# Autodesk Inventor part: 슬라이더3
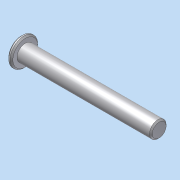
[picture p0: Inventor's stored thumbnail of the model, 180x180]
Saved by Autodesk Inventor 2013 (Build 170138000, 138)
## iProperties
Company: 한국ATC센터
Created: 2015-04
Part Number: 슬라이더3
Document SubType Name: Modeling
Designer: KYOUNG IL JANG
Density: 1 g/cm^3
Material: 강철
Mass: 11.8344 g
Surface Area: 43.7403 cm^2
Volume: 11.8344 cm^3
Author: KYOUNG IL JANG
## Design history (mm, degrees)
sketch "스케치1"
  geometry: L1 (0, 0)-(0, 10); L2 (0, 10)-(-3, 10); L3 (-3, 10)-(-3, 6); L4 (-3, 6)-(-100, 6); L5 (-100, 6)-(-100, 0); L6 (-100, 0)-(0, 0)
  constraints: 12 end point, 4 parallel, 1 perpendicular, 1 vertical
  dimensions: "d0" = 12 diameter of L4 L6; "d1" = 20 diameter of L2 L6; "d2" = 3 distance between parallel lines of L3 L1; "d3" = 100 distance between parallel lines of L5 L1
revolve "회전1" sketch "스케치1" stored, may be unused: angle "d4" = 90 deg
chamfer "모따기1" distance "d5" = 1; stored, may be unused: second distance "d6" = 2, angle "d7" = 45 deg
node "솔리드1"
